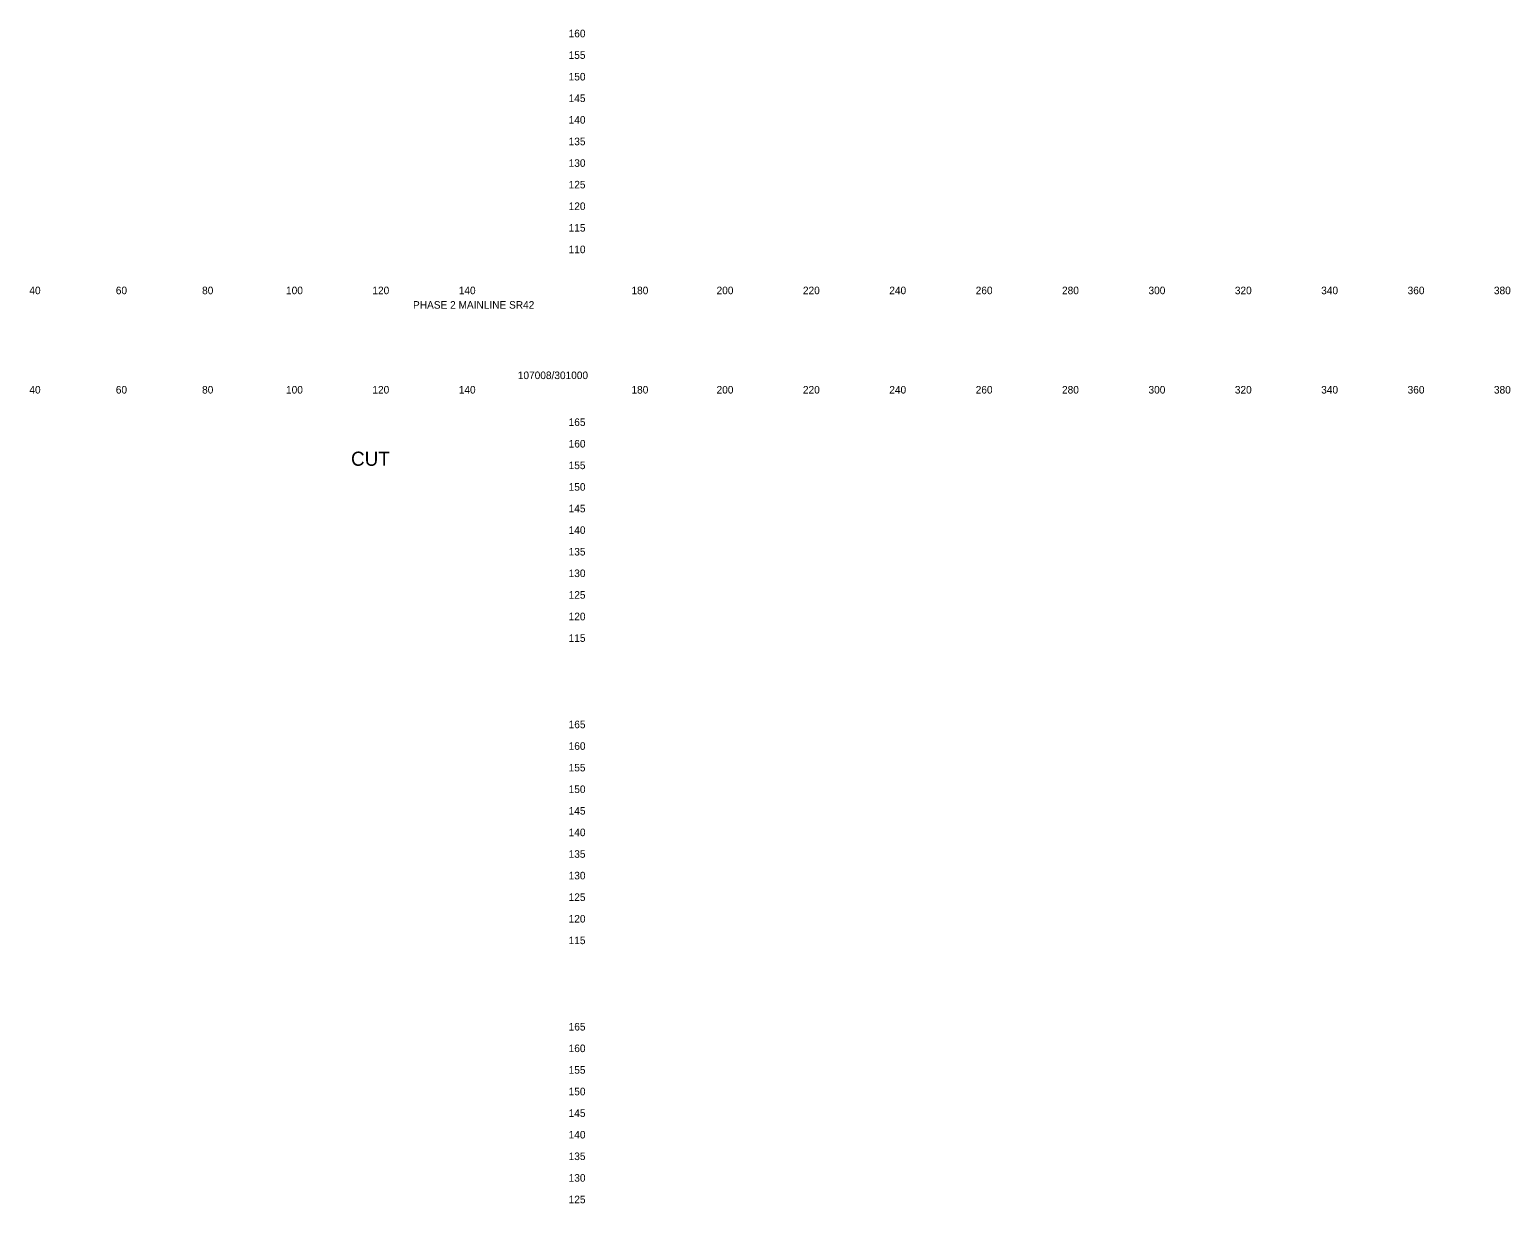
# Model space of a CAD drawing. Extents: x 21281 to 22024, y 6472 to 15208.
# Drawn here: x 21681.3 to 22024.2, y 8104.8 to 8376.6 of the extents above; entities that cross this region are included whole.
import ezdxf

# ---------------------------------------------------------------- set-up
doc = ezdxf.new("R2010")
doc.units = 0
doc.layers.add('XS_SHEET_LABELS_ELEVATION', color=7, linetype='Continuous')
doc.layers.add('XS_SHEET_LABELS_OFFSET', color=7, linetype='Continuous')

msp = doc.modelspace()

# ---------------------------------------------------------------- texts
at = {"layer": 'XS_SHEET_LABELS_ELEVATION'}
for s, p in [('  160  ', (21804.84, 8374.84)), ('  155  ', (21804.84, 8369.84)), ('  150  ', (21804.84, 8364.84)), ('  145  ', (21804.84, 8359.84)), ('  140  ', (21804.84, 8354.84)), ('  135  ', (21804.84, 8349.84)), ('  130  ', (21804.84, 8344.84)), ('  125  ', (21804.84, 8339.84)), ('  120  ', (21804.84, 8334.84)), ('  115  ', (21804.84, 8329.84)), ('  110  ', (21804.84, 8324.84)), ('  165  ', (21804.84, 8284.84)), ('  160  ', (21804.84, 8279.84)), ('  155  ', (21804.84, 8274.84)), ('  150  ', (21804.84, 8269.84)), ('  145  ', (21804.84, 8264.84)), ('  140  ', (21804.84, 8259.84)), ('  135  ', (21804.84, 8254.84)), ('  130  ', (21804.84, 8249.84)), ('  125  ', (21804.84, 8244.84)), ('  120  ', (21804.84, 8239.84)), ('  115  ', (21804.84, 8234.84)), ('  165  ', (21804.84, 8214.84)), ('  160  ', (21804.84, 8209.84)), ('  155  ', (21804.84, 8204.84)), ('  150  ', (21804.84, 8199.84)), ('  145  ', (21804.84, 8194.84)), ('  140  ', (21804.84, 8189.84)), ('  135  ', (21804.84, 8184.84)), ('  130  ', (21804.84, 8179.84)), ('  125  ', (21804.84, 8174.84)), ('  120  ', (21804.84, 8169.84)), ('  115  ', (21804.84, 8164.84)), ('  165  ', (21804.84, 8144.84)), ('  160  ', (21804.84, 8139.84)), ('  155  ', (21804.84, 8134.84)), ('  150  ', (21804.84, 8129.84)), ('  145  ', (21804.84, 8124.84)), ('  140  ', (21804.84, 8119.84)), ('  135  ', (21804.84, 8114.84)), ('  130  ', (21804.84, 8109.84)), ('  125  ', (21804.84, 8104.84))]:
    msp.add_text(s, height=1.75, dxfattribs=at).set_placement(p)
at = {"layer": 'XS_SHEET_LABELS_OFFSET'}
for s, height, p in [('  40  ', 1.75, (21679.95, 8315.34)), ('  60  ', 1.75, (21699.97, 8315.34)), ('  80  ', 1.75, (21719.95, 8315.34)), ('  100  ', 1.75, (21739.39, 8315.34)), ('  120  ', 1.75, (21759.39, 8315.34)), ('  140  ', 1.75, (21779.39, 8315.34)), ('  180  ', 1.75, (21819.39, 8315.34)), ('  200  ', 1.75, (21839.1, 8315.34)), ('  220  ', 1.75, (21859.1, 8315.34)), ('  240  ', 1.75, (21879.1, 8315.34)), ('  260  ', 1.75, (21899.11, 8315.34)), ('  280  ', 1.75, (21919.1, 8315.34)), ('  300  ', 1.75, (21939.13, 8315.34)), ('  320  ', 1.75, (21959.13, 8315.34)), ('  340  ', 1.75, (21979.13, 8315.34)), ('  360  ', 1.75, (21999.14, 8315.34)), ('  380  ', 1.75, (22019.13, 8315.34)), ('PHASE 2 MAINLINE SR42', 1.75, (21770.1, 8311.99)), ('107008/301000', 1.75, (21794.37, 8295.69)), ('  40  ', 1.75, (21679.95, 8292.34)), ('  60  ', 1.75, (21699.97, 8292.34)), ('  80  ', 1.75, (21719.95, 8292.34)), ('  100  ', 1.75, (21739.39, 8292.34)), ('  120  ', 1.75, (21759.39, 8292.34)), ('  140  ', 1.75, (21779.39, 8292.34)), ('  180  ', 1.75, (21819.39, 8292.34)), ('  200  ', 1.75, (21839.1, 8292.34)), ('  220  ', 1.75, (21859.1, 8292.34)), ('  240  ', 1.75, (21879.1, 8292.34)), ('  260  ', 1.75, (21899.11, 8292.34)), ('  280  ', 1.75, (21919.1, 8292.34)), ('  300  ', 1.75, (21939.13, 8292.34)), ('  320  ', 1.75, (21959.13, 8292.34)), ('  340  ', 1.75, (21979.13, 8292.34)), ('  360  ', 1.75, (21999.14, 8292.34)), ('  380  ', 1.75, (22019.13, 8292.34)), ('CUT', 3.273, (21755.74, 8275.61))]:
    msp.add_text(s, height=height, dxfattribs=at).set_placement(p)

doc.saveas('drawing.dxf')
